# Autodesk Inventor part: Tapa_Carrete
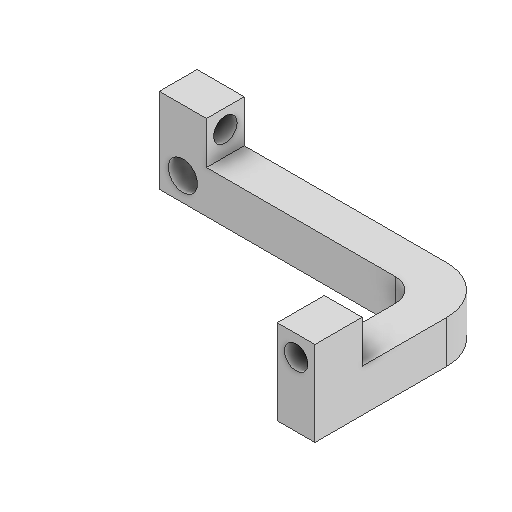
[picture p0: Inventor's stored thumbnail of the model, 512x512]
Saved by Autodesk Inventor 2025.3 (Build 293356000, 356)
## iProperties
Created: 2025-12
Part Number: Tapa_Carrete
Material: Genérico
Document SubType Name: Modeling
Designer: Sebastian Chiriboga
Density: 1 g/cm^3
Appearance: Valor por defecto
Author: Sebastian Chiriboga
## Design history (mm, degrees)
sketch "Boceto1"
  geometry: L1 (-5, 9)-(5, 9); L2 (5, 9)-(5, -9); L3 (5, -9)-(-5, -9); L4 (-5, -9)-(-5, 9); L5 (-5, 9)-(5, -9); L6 (5, 9)-(-5, -9); L7 (0, -9)-(5, -9); C1 r 3.1 at (0, -4); 1 further point
  constraints: 14 end point, 3 midpoint, 2 horizontal, 2 parallel, 1 centre point, 1 perpendicular
  dimensions: "d4" = 6.2 diameter of C1
extrude "Extrusión1" new body sketch "Boceto1" distance "d5" = 8; taper "d6" = 0 deg
sketch "Boceto2"
  geometry: L1 (-8, 0)-(-8, 18) reference; L2 (-8, 18)-(0, 18); L3 (0, 18)-(0, 0); L4 (0, 0)-(-8, 0); L5 (-8, 0)-(-8, 18); 2 further points
  constraints: 8 end point, 2 parallel, 1 horizontal, 1 perpendicular
extrude "Extrusión2" join sketch "Boceto2" distance "d7" = 45; taper "d8" = 0 deg
sketch "Boceto3"
  geometry: L1 (-8, 18)-(0, 18); L2 (0, 18)-(0, 0); L3 (0, 0)-(-8, 0); L4 (-8, 0)-(-8, 18); 1 further point
  constraints: 8 end point, 2 parallel, 1 horizontal, 1 perpendicular
extrude "Extrusión3" join sketch "Boceto3" distance "d9" = 8; taper "d10" = 0 deg
sketch "Boceto4"
  geometry: L1 (58, 9)-(58, -9) reference; L2 (-5, -9)-(58, -9) reference; L3 (58, 9)-(50, 9); L4 (50, 9)-(50, -9); L5 (50, -9)-(58, -9); L6 (58, -9)-(58, 9); 1 further point
  constraints: 8 end point, 2 parallel, 1 horizontal, 1 perpendicular, 1 point on line
  dimensions: "d11" = 8 distance of L5.end L4.end
extrude "Extrusión4" join sketch "Boceto4" distance "d12" = 30; taper "d13" = 0 deg
sketch "Boceto5"
  geometry: L1 (0, 18)-(8, 18) reference; C1 r 2.5 at (4, 14); 1 further point
  constraints: 1 centre point
  dimensions: "d15" = 5 diameter of C1
extrude "Extrusión5" cut sketch "Boceto5" distance "d16" = 40; taper "d17" = 0 deg
fillet "Empalme1" dims "d20" = 5
fillet "Empalme2" dims "d21" = 10
sketch "Boceto7"
  geometry: L1 (-5, 9)-(-5, -9) reference; L2 (-5, 9)-(5, 9); L3 (-5, 9)-(48, 9) reference; L4 (50, 9)-(50, -9) reference; L5 (5, 9)-(50, 9); L6 (50, 9)-(50, 0); L7 (50, 0)-(5, 0); L8 (5, 0)-(5, 9); 3 further points
  constraints: 10 end point, 2 parallel, 1 horizontal, 1 midpoint, 1 perpendicular, 1 point on line
  dimensions: "d24" = 10 distance of L1.start L2.end
extrude "Extrusión7" cut sketch "Boceto7" stored distance "d25" = 31.25; taper "d26" = 0 deg
sketch "Boceto8"
  geometry: L1 (0, 18)-(0, 0) reference; L2 (0, 18)-(-10, 18); L3 (-37.798, 18)-(0, 18) reference; L4 (-30, 9)-(-38, 9) reference; L5 (-10, 18)-(-38, 18); L6 (-38, 18)-(-38, 9); L7 (-38, 9)-(-10, 9); L8 (-10, 9)-(-10, 18); 2 further points
  constraints: 10 end point, 2 parallel, 1 horizontal, 1 perpendicular, 1 point on line
  dimensions: "d27" = 10 distance of L1.start L2.end
extrude "Extrusión8" cut sketch "Boceto8" distance "d28" = 31.25; taper "d29" = 0 deg
sketch "Boceto9"
  geometry: C1 r 2.5 at (54.012, 4.647); C2 r 2.5 at (54.012, -4.647); 1 further point
  constraints: 2 centre point
  dimensions: "d30" = 5 diameter of C1; "d31" = 5 diameter of C2
extrude "Extrusión9" cut sketch "Boceto9" extent not by distance; stored distance "d32" = 0; taper "d33" = 0 deg
node "Sólido1"
